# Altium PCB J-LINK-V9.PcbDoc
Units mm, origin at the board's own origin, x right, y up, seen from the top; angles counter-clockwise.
Board outline 88.57 x 38.68 mm, 2 copper layers (Top Layer, Bottom Layer); 76 components, 83 nets, 372 pads, 106 vias.
Unrouted connection lines stored in the file: 2.
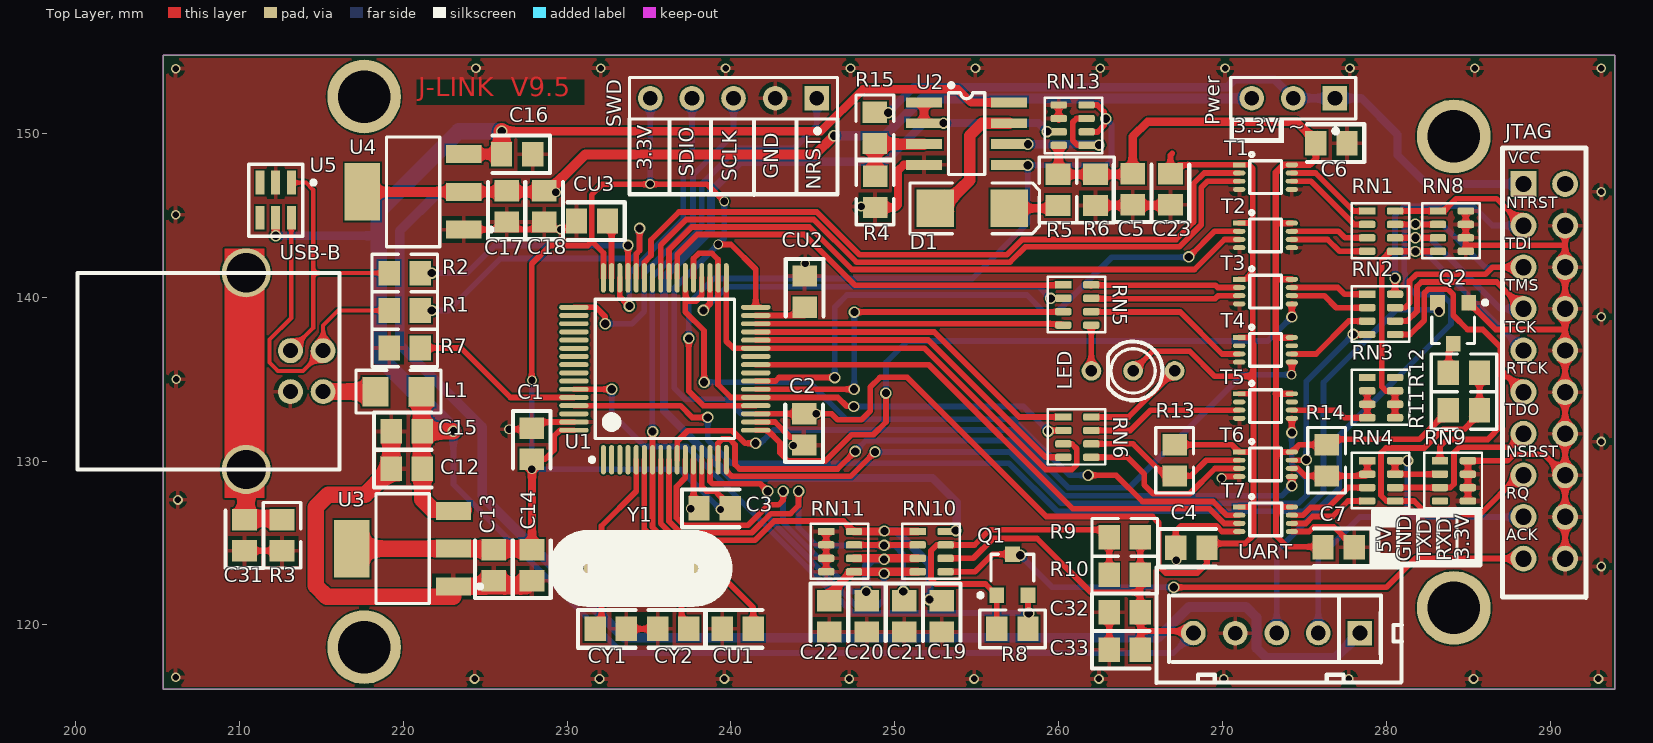
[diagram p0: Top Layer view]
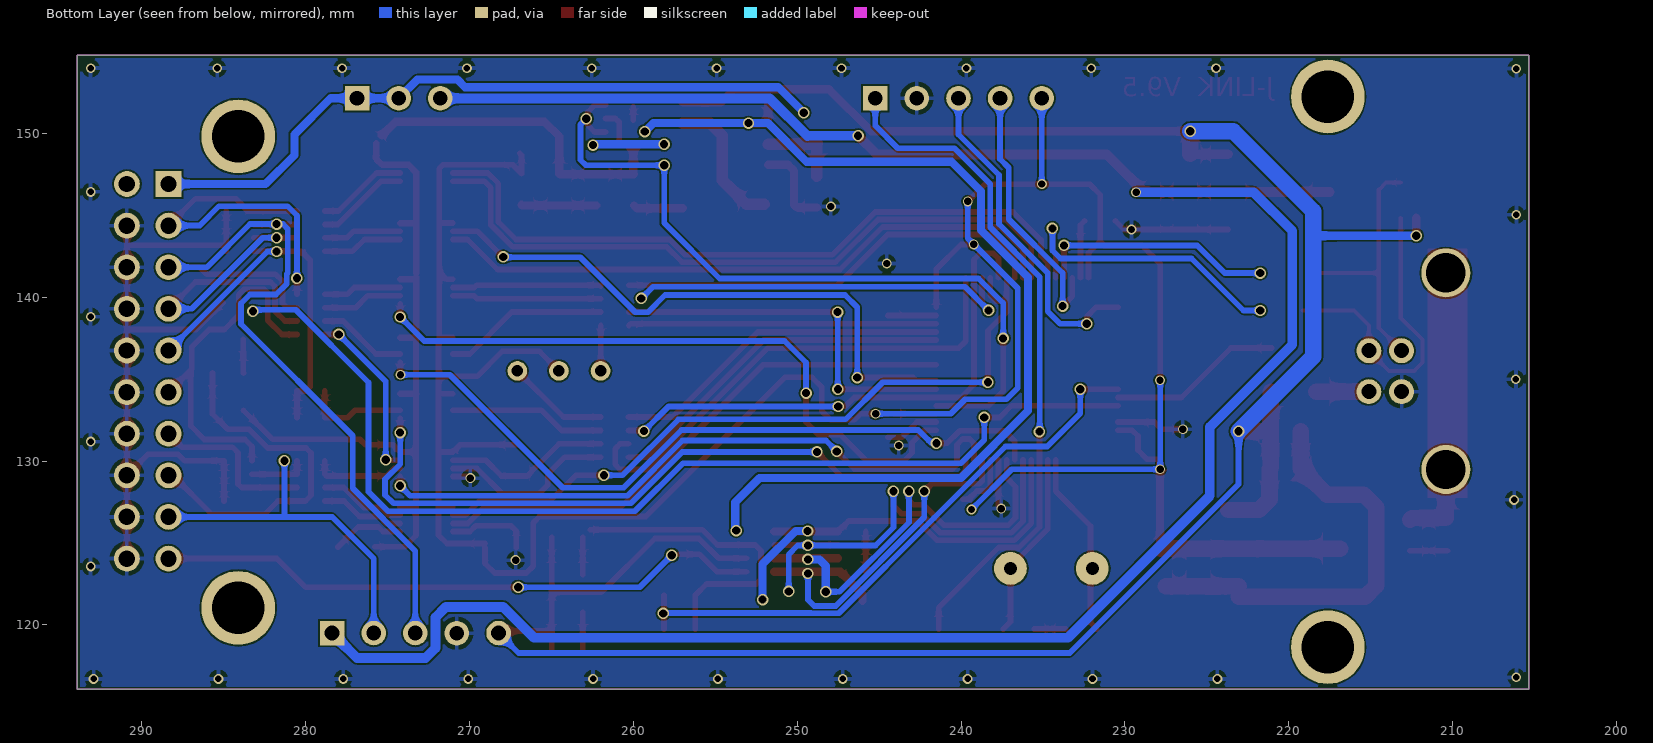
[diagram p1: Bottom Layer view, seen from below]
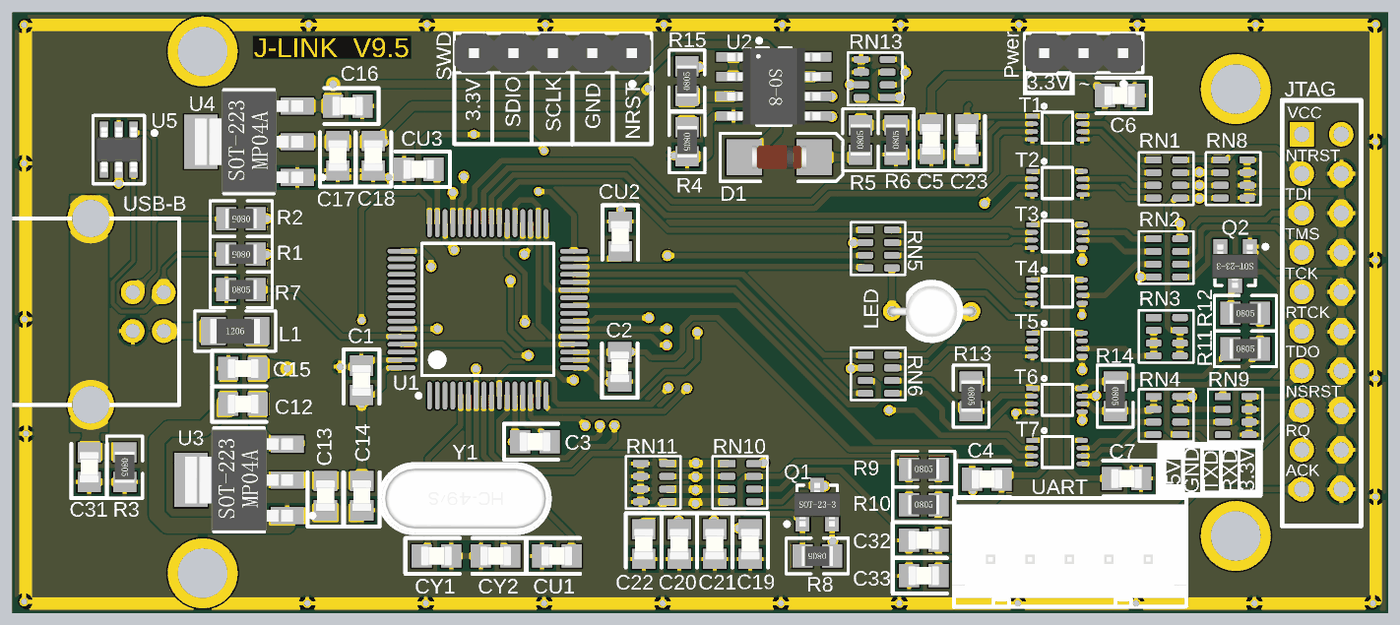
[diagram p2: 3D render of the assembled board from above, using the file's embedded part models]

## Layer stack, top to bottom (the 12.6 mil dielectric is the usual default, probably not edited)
Top Solder: solder mask 0.0102, Solder Resist, Dk 3.5
Top Layer: signal copper 0.0356
Dielectric 1: dielectric 0.32, FR-4, Dk 4.8
Bottom Layer: signal copper 0.0356
Bottom Solder: solder mask 0.0102, Solder Resist, Dk 3.5

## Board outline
205.359,116.078 293.929,116.078 293.929,154.762 205.359,154.762

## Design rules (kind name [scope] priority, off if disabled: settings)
Clearance [All] p1: gap=0.1
PolygonConnect [All] p1: connectstyle=Relief reliefconductorwidth=0.254 reliefentries=4 polygonreliefangle="90 Angle" airgapwidth=0.254
RoutingVias [All] p1: holewidth=0.711 width=1.27 viastyle="Through Hole" minholewidth=0.711 minwidth=1.27 maxholewidth=0.711 maxwidth=1.27
SolderMaskExpansion [All] p1: expansion=0.102
Width [All] p1: maxlimit=2.54 minlimit=2539.975 preferedwidth=0.254 toplayer_minwidth=0 bottomlayer_minwidth=0 minimp=50.000000 maximp=50.000000 favimp=50.000000
30 further rules are at their usual default settings.

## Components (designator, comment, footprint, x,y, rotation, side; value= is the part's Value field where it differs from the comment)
C1 "104" CC2012-0805 227.838,131.064 r270 top
C2 "104" CC2012-0805 244.461,131.939 r90 top
C3 "104" CC2012-0805 239.005,127.119 r0 top
C4 "104" CC2012-0805 268.1,124.706 r0 top
C5 "104" CC2012-0805 264.516,146.591 r90 top (schematic designator C24)
C6 "104" CC2012-0805 276.647,149.406 r180 top (schematic designator C25)
C7 "104" CC2012-0805 277.083,124.746 r180 top (schematic designator C26)
C12 "104" CC2012-0805 220.218,129.54 r0 top
C13 "104" CC2012-0805 225.52,123.648 r90 top
C14 "226" CC2012-0805 227.857,123.648 r90 top
C15 "106" CC2012-0805 220.218,131.826 r0 top
C16 "104" CC2012-0805 226.95,148.728 r180 top
C17 "104" CC2012-0805 226.314,145.542 r90 top
C18 "226" CC2012-0805 228.6,145.542 r90 top
C19 "Cap Chip" CC2012-0805 252.864,120.523 r270 top
C20 "Cap Chip" CC2012-0805 248.292,120.523 r270 top
C21 "Cap Chip" CC2012-0805 250.578,120.523 r270 top
C22 "Cap Chip" CC2012-0805 246.006,120.523 r270 top
C23 "106" CC2012-0805 266.822,146.591 r90 top
C31 "Cap Chip" CC2012-0805 210.312,125.476 r90 top
C32 "Cap Chip" CC2012-0805 264.033,120.777 r0 top
C33 "Cap Chip" CC2012-0805 264.033,118.491 r0 top
CU1 "Cap Chip" CC2012-0805 240.411,119.761 r0 top
CU2 "Cap Chip" CC2012-0805 244.491,140.344 r270 top
CU3 "Cap Chip" CC2012-0805 231.521,144.653 r180 top
CY1 "Cap Chip" CC2012-0805 232.664,119.761 r0 top
CY2 "Cap Chip" CC2012-0805 236.474,119.761 r180 top
D1 "Diode SMT" DSO-C2/X2.3 254.727,145.427 r0 top
JTAG "Header 10X2" IDC2.54-20 288.366,146.914 r270 top locked
L1 "Resistor Chip" CR3216-1206 219.71,134.239 r0 top
LED "LED-3-DOUBLE" LED-R3-H5-DOUBLE 264.541,135.509 r180 top locked
Pwer "Header 3" HDR1X3 276.86,152.146 r180 top
Q1 "PNP-8550" SO-G3/C2.5 257.175,123.063 r0 top
Q2 "NPN-8050" SO-G3/C2.5 284.076,138.422 r180 top
R1 "Resistor Chip" CR2012-0805 220.091,139.192 r180 top
R2 "Resistor Chip" CR2012-0805 220.091,141.478 r180 top
R3 "Resistor Chip" CR2012-0805 212.598,125.476 r270 top
R4 "Resistor Chip" CR2012-0805 248.793,146.431 r270 top
R5 "Resistor Chip" CR2012-0805 259.958,146.555 r90 top
R6 "Resistor Chip" CR2012-0805 262.246,146.555 r90 top
R7 "Resistor Chip" CR2012-0805 220.091,136.906 r0 top
R8 "Resistor Chip" CR2012-0805 257.175,119.761 r180 top
R9 "Resistor Chip" CR2012-0805 264.033,125.349 r0 top
R10 "Resistor Chip" CR2012-0805 264.033,123.063 r0 top
R11 "Resistor Chip" CR2012-0805 284.734,133.096 r0 top
R12 "Resistor Chip" CR2012-0805 284.734,135.382 r0 top
R13 "Resistor Chip" CR2012-0805 267.081,130.048 r270 top
R14 "Resistor Chip" CR2012-0805 276.352,130.048 r270 top
R15 "Resistor Chip" CR2012-0805 248.781,150.338 r90 top
RN1 "RESNET 4 x 220R" SDR 279.654,144.018 r0 top
RN2 "RESNET 4 x 220R" SDR 279.654,138.938 r0 top
RN3 "RESNET 4 x 220R" SDR 279.654,133.858 r0 top
RN4 "RESNET 4 x 220R" SDR 279.654,128.778 r0 top
RN5 "RESNET 4 x 220R" SDR 261.105,139.514 r0 top
RN6 "RESNET 4 x 220R" SDR 261.112,131.445 r0 top
RN8 "RESNET 4 x 220K" SDR 283.972,144.018 r0 top
RN9 "RESNET 4 x 220K" SDR 284.099,128.778 r0 top
RN10 "RESNET 4 x 10K" SDR 252.222,124.46 r0 top
RN11 "RESNET 4 x 10K" SDR 246.634,124.46 r0 top
RN13 "RESNET 4 x 10K" SDR 260.881,150.521 r180 top
SWD "Header 5" HDR1X5 245.237,152.146 r180 top
T1 "2T45" SSOP8 271.018,148.082 r0 top
T2 "2T45" SSOP8 271.018,144.526 r0 top
T3 "2T45" SSOP8 271.018,141.097 r0 top
T4 "2T45" SSOP8 271.018,137.541 r0 top
T5 "2T45" SSOP8 271.018,134.112 r0 top
T6 "2T45" SSOP8 271.018,130.556 r0 top
T7 "2T45" SSOP8 271.021,127.2 r0 top
U1 "STM32F205RCT6" LQFP64_N 235.966,135.636 r90 top
U2 "LM358" SOP-8 254.381,149.987 r270 top locked
U3 "AMS1117-3.3" SOT-223 219.96,124.655 r90 top
U4 "AMS1117-3.3" SOT-223 220.599,146.431 r90 top
U5 "NUP4201" SOP-6 212.217,145.923 r180 top
UART "Header 5" HX2.54-5 278.384,119.507 r180 top
USB-B "Header 6" USB-B 215.113,134.239 r0 top locked
Y1 "XTAL" XTAL-PINGBI 236.986,123.451 r180 top

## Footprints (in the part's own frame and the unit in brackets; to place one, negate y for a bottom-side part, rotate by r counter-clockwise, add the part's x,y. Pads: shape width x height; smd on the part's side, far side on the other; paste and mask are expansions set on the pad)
CC2012-0805 [mm]
  rect 1.3x1.5 smd: 1(-0.95,0) 2(0.95,0)
  silkscreen extent -2,-1.15 1.5,1.15, body extent -1,-0.62 1,0.63, height 0.5
CR2012-0805 [mm]
  rect 1.3x1.5 smd: 1(-0.95,0) 2(0.95,0)
  silkscreen extent -2,-1.15 2,1.15, body extent -1,-0.63 1,0.63, height 0.55
CR3216-1206 [mm]
  rect 1.6x1.8 smd: 1(-1.4,0) 2(1.4,0)
  silkscreen extent -2.6,-1.3 2.6,1.3, body extent -1.6,-0.8 1.6,0.8, height 0.6
DSO-C2/X2.3 [mm]
  rect 2.3x2.3 smd: 1(-2.25,0) 2(2.25,0)
  silkscreen extent -3.8,-1.55 4.1,1.55, body extent -1.75,-0.75 1.75,0.75, height 1.5
HDR1X3 [mm] "Connector; Header; 3 Position"
  rect 1.5x1.5 hole 0.9: 1(0,0)
  round 1.5 hole 0.9: 2(2.54,0) 3(5.08,0)
  silkscreen extent -1.27,-1.27 6.35,2.14, body extent -1.27,-1.27 6.35,1.27, height 8.54
HDR1X5 [mm] "Connector; Header; 5 Position"
  rect 1.5x1.5 hole 0.9: 1(0,0)
  round 1.5 hole 0.9: 2(2.54,0) 3(5.08,0) 4(7.62,0) 5(10.16,0)
  silkscreen extent -1.27,-1.27 11.43,2.14, body extent -1.27,-1.27 11.43,1.27, height 8.54
HX2.54-5 [mm]
  rect 1.5x1.5 hole 0.9: 1(0,0)
  round 1.5 hole 0.9: 2(2.54,0) 3(5.08,0) 4(7.607,0.006) 5(10.16,0)
  silkscreen extent -2.55,-4.06 12.42,3.05, body extent -2.56,-3.56 12.52,2.44, height 7.51
IDC2.54-20 [mil]
  rect 62x62 hole 39.37: 1(0,0)
  round 62 hole 39.37: 2(0,100) 3(100,0) 4(100,100) 5(200,0) 6(200,100) 7(300,0) 8(300,100) 9(400,0) 10(400,100) 11(500,0) 12(500,100) 13(600,0) 14(600,100) 15(700,0) 16(700,100) 17(800,0) 18(800,100) 19(900,0) 20(900,100)
  silkscreen extent -86,-50 994,150
LED-R3-H5-DOUBLE [mm]
  round 1.2 hole 0.7: 1(0,0) 2(-2.54,0) 3(2.54,0)
  silkscreen extent -1.8,-1.79 1.52,1.79, body extent -2.79,-2.04 2.79,2.04, height 5.7
LQFP64_N [mm]
  oval 1.8x0.3 smd: 1(-5.55,3.75) 2(-5.55,3.25) 3(-5.55,2.75) 4(-5.55,2.25) 5(-5.55,1.75) 6(-5.55,1.25) 7(-5.55,0.75) 8(-5.55,0.25) 9(-5.55,-0.25) 10(-5.55,-0.75) 11(-5.55,-1.25) 12(-5.55,-1.75) 13(-5.55,-2.25) 14(-5.55,-2.75) 15(-5.55,-3.25) 16(-5.55,-3.75) 33(5.55,-3.75) 34(5.55,-3.25) 35(5.55,-2.75) 36(5.55,-2.25) 37(5.55,-1.75) 38(5.55,-1.25) 39(5.55,-0.75) 40(5.55,-0.25) 41(5.55,0.25) 42(5.55,0.75) 43(5.55,1.25) 44(5.55,1.75) 45(5.55,2.25) 46(5.55,2.75) 47(5.55,3.25) 48(5.55,3.75)
  oval 0.3x1.8 smd: 17(-3.75,-5.55) 18(-3.25,-5.55) 19(-2.75,-5.55) 20(-2.25,-5.55) 21(-1.75,-5.55) 22(-1.25,-5.55) 23(-0.75,-5.55) 24(-0.25,-5.55) 25(0.25,-5.55) 26(0.75,-5.55) 27(1.25,-5.55) 28(1.75,-5.55) 29(2.25,-5.55) 30(2.75,-5.55) 31(3.25,-5.55) 32(3.75,-5.55) 49(3.75,5.55) 50(3.25,5.55) 51(2.75,5.55) 52(2.25,5.55) 53(1.75,5.55) 54(1.25,5.55) 55(0.75,5.55) 56(0.25,5.55) 57(-0.25,5.55) 58(-0.75,5.55) 59(-1.25,5.55) 60(-1.75,5.55) 61(-2.25,5.55) 62(-2.75,5.55) 63(-3.25,5.55) 64(-3.75,5.55)
  silkscreen extent -5.67,-4.25 4.25,4.57
SDR [mm]
  rect 1x0.45 smd: 1(-0.824,1.248)
  rrect50% 1x0.45 smd: 2(-0.824,0.427) 3(-0.824,-0.393) 4(-0.824,-1.212) 5(0.875,-1.212) 6(0.875,-0.393) 7(0.875,0.427) 8(0.875,1.248)
  silkscreen extent -1.78,-1.65 1.74,1.73
SO-G3/C2.5 [mm]
  rect 0.9x0.95 smd: 1(-0.95,-1.25) 2(0.95,-1.25) 3(0,1.25)
  silkscreen extent -2.07,-1.37 1.3,1.25, body extent -1.45,-1.4 1.45,1.4, height 1.2
SOP-6 [mm]
  rect 0.55x1.45 smd: 1(-0.95,-1.075) 2(0,-1.075) 3(0.95,-1.075) 4(0.95,1.075) 5(0,1.075) 6(-0.95,1.075)
  silkscreen extent -2.43,-2.2 1.65,2.2, body extent -1.48,-1.43 1.49,1.43, height 1.26
SOP-8 [mm]
  rect 0.6x2.2 smd: 1(-1.905,-2.6) 2(-0.635,-2.6) 3(0.635,-2.6) 4(1.905,-2.6) 5(1.905,2.6) 6(0.635,2.6) 7(-0.635,2.6) 8(-1.905,2.6)
  silkscreen extent -3.07,-1.1 2.5,1.1, body extent -2.45,-3 2.45,3, height 1.7
SOT-223 [mm]
  rect 1.1x2.15 smd: 1(-2.3,-3.1) 2(0,-3.1) 3(2.3,-3.1)
  rect 3.5x2.15 smd: 2(0,3.1)
  silkscreen extent -3.35,-4.85 3.35,1.63, body extent -3.25,-3.48 3.25,3.48, height 1.7
SSOP8 [mm]
  rect 0.75x0.3 smd: 1(0,0)
  oval 0.75x0.3 smd: 2(0,-0.5) 3(0,-1) 4(0,-1.5) 5(3.212,-1.5) 6(3.212,-1) 7(3.212,-0.5) 8(3.212,0)
  silkscreen extent 0.64,-1.75 2.59,0.76, body extent 0.51,-1.91 2.73,0.38, height 1.3
USB-B [mm]
  round 1.524 hole 0.92: 1(0,0) 2(0,2.5) 3(-2,2.5) 4(-2,0)
  round 3 hole 2.4: 5(-4.7,7.25) 6(-4.7,-4.75)
  silkscreen extent -15,-4.75 1,7.25, body extent -15.05,-4.8 1.11,7.32, height 10.1
XTAL-PINGBI [mm]
  round 2 hole 0.8: 1(0,0) 2(5,0)
  silkscreen extent -3,-2.25 8,2.26, body extent -2.95,-2.26 7.85,2.24, height 3.5

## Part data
C1 C2 C3 C4 C5 C6 C7 C12 C13 C14 C15 C16 C17 C18 C23: library part "Cap Chip", "Polarized Capacitor (Radial)"
C19 C20 C21 C22 C31 C32 C33 CU1 CU2 CU3 CY1 CY2: "Polarized Capacitor (Radial)"
D1: "Default Diode"
JTAG: "Header, 10-Pin, Dual row"
L1 R1 R2 R3 R4 R5 R6 R7 R8 R9 R10 R11 R12 R13 R14 R15: "Resistor"
LED: "Typical INFRARED GaAs LED"
Pwer: "Header, 3-Pin"
Q1: library part PNP-SMT, "PNP Bipolar Transistor"
Q2: library part NPN-SMT, "NPN Bipolar Transistor"
RN1 RN2 RN3 RN4 RN5 RN6 RN8 RN9 RN10 RN11 RN13: library part "Res Pack SMT4", "Resistor Network, Isolated, 4 x 100R, 5%, SMD 0402 x 4"
SWD UART: "Header, 5-Pin"
T1 T2 T3 T4 T5 T6 T7: library part Component_1
U1: library part STM32F103RDT6
U2: library part LM393
U3 U4: library part AMS1117, "POSITIVE OUTPUT VOLTAGE"
U5: library part USBLC6
USB-B: "Header, 6-Pin"
Y1: "Crystal Oscillator"

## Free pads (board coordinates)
  round 4.5 hole 3.2: 0(217.614,118.646) 0(217.614,152.246) 0(284.114,121.046) 0(284.114,149.821)

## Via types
v1: diameter 0.7, hole 0.5, Top Layer to Bottom Layer, 60 vias
v2: diameter 0.6, hole 0.4, Top Layer to Bottom Layer, 29 vias
v3: diameter 0.6, hole 0.45, Top Layer to Bottom Layer, 17 vias

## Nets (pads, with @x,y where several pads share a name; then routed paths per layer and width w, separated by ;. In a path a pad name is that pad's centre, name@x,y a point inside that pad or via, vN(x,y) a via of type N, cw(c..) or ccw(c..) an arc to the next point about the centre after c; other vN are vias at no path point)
3.3V-A: C1.2 C2.2 C3.2 C4.2 C13.2 C14.2 C23.2 LED.1 R13.1 SWD.5 T1.1 T2.1 T3.1 T4.1 T5.1 T6.1 T7.1 U1.13 U1.19 U1.32 U1.48 U1.64 U3.2 | length 186.2
  Top Layer w0.35: C1.2 228.644,130.114 229.206,130.676 229.206,131.532 229.561,131.886 U1.64 ; v3@227.843,135.078 227.843,142.05 228.954,143.161 231.258,143.161 231.496,143.398 231.496,146.248 232.146,146.898 238.543,146.898 v3(239.591,145.851) ; 231.441,143.344 231.579,143.344 232.216,142.706 U1.48 ; U1.13 238.216,128.442 238.487,128.17 239.034,128.17 239.524,127.68 C3.2@239.878,127.68 ; v3(239.226,143.226) 239.994,143.226 241.516,141.704 U1.32 ; U1.19 C2.2@244.111,132.886 ; C2.2 246.144,132.889 246.507,132.526 247.967,132.526 248.499,133.059 248.499,134.519 249.091,135.111 250.762,135.111 259.246,126.627 265.724,126.627 266.11,126.24 266.11,123.586 266.531,123.166 268.458,123.166 269.05,123.758 C4.2 ; LED.1 265.73,136.698 268.007,136.698 269.531,135.174 271.883,135.174 ; 266.931,148.783 266.822,148.675 C23.2 267.363,148.082 T1.1 271.615,148.082 271.852,147.845 271.852,141.543 ; R13.1 270.576,130.998 T6.1 271.792,130.556 ; C4.2@269.05,124.968 271.373,124.968 271.883,125.478 271.883,135.174 ; T5.1 271.869,134.112 ; T4.1 271.714,137.541 271.852,137.403 ; T3.1 271.406,141.097 271.852,141.543 ; T2.1 271.843,144.526 ; T7.1 271.832,127.2 ; 271.852,137.112 271.852,137.403 ; 271.883,137.112 271.883,135.174 ; 271.852,137.403 271.852,141.543
  Top Layer w0.5: C14.2 C1.2@227.857,129.833
  Top Layer w1: U3.2@216.86,124.655 223.06,124.655 C14.2@227.8,124.655
  Bottom Layer w0.35: v3(227.856,134.933) 227.849,134.926 v3(227.849,129.501) 236.908,129.501 v3(239.359,127.05) ; v3(235.065,146.912) 235.077,146.924 SWD.5 ; v3@239.59,145.912 239.59,143.596 236.543,140.548 236.543,134.463 237.229,133.777 239.74,133.777 240.629,132.888 v3(245.213,132.888)
3.3V-B: C17.2 C18.2 Pwer.3 U4.2 UART.1 | length 146.2
  Top Layer w0.6: U4.2@217.499,146.431 228.539,146.431 C18.2 228.883,146.492 231.105,148.714 245.141,148.714 v1(246.283,149.857)
  Bottom Layer w0.6: v3(229.316,146.41) 222.155,146.41 219.783,144.037 219.783,137.119 224.818,132.084 224.818,127.886 233.481,119.223 266.063,119.223 267.935,121.095 271.447,121.095 272.075,120.467 272.075,118.583 272.679,117.979 276.856,117.979 UART.1 ; v1(246.283,149.857) 249.364,149.857 249.378,149.843 251.673,152.138 271.331,152.138 Pwer.3@271.552,151.918
5V: C12.2 C15.2 C16.2 C32.2 C33.2 L1.2 R9.2 R10.2 RN10.6 U2.8 U3.3 U4.3 U5.5 UART.5 | length 156.3
  Top Layer w0.35: RN10.6 254.79,124.067 256.007,125.285 258.672,125.285 261.962,121.995 264.983,121.995 ; C33.2 264.983,119.627 ; R9.2 R10.2 264.983,121.995 ; UART.5@268.104,119.627 264.983,119.627 ; 264.983,119.627 C32.2 264.983,121.995
  Top Layer w0.5: v1@212.217,143.918 U5.5 ; v1(226.017,150.138) 245.494,150.138 248.046,152.69 253.861,152.69 254.66,151.892 U2.8
  Top Layer w0.6: U4.3 225.998,148.731 C16.2
  Top Layer w1: C12.2@221.11,129.598 L1.2 ; C12.2 221.168,127.658 221.812,127.014 U3.3@223.699,127.014 ; C15.2 v1@223.061,131.826 ; C16.2@226.017,148.745 v1(226.017,150.138)
  Bottom Layer w0.35: v1(223.062,131.826) 223.062,128.593 233.371,118.284 267.001,118.284 UART.5
  Bottom Layer w0.5: v1(212.218,143.754) 218.555,143.754
  Bottom Layer w1: v1(223.062,131.826) 218.499,136.389 218.499,145.256 223.381,150.138 v1(226.017,150.138)
ACK-D: RN10.8 RN13.7 U2.1 U2.2 | length 61.4
  Top Layer w0.5: U2.1 U2.2 v1@252.97,150.622
  Bottom Layer w0.5: v1@253.785,125.811 253.785,127.486 252.293,128.979 240.011,128.979 235.917,133.073 235.917,141.221 238.786,144.09 238.786,146.469 240.586,148.269 249.43,148.269 251.788,150.627 v1(252.97,150.627) 258.782,150.627 v1(259.3,150.11)
  other v1: 253.724,125.763
BOOT0: R7.2 U1.60 | length 10.6
  Top Layer w0.35: R7.2 223.52,136.906 226.54,133.886 U1.60
BOOT1: RN6.4 U1.28 | length 21.7
  Top Layer w0.35: U1.28 252.039,137.386 259.192,130.233 RN6.4
BOOT2: U1.58
BOOT3: U1.57
DM: R1.1 U1.44 | length 18.6
  Top Layer w0.35: U1.44 234.216,142.649 234.422,142.855 v1(234.422,144.201)
  Bottom Layer w0.35: v1(221.742,139.192) 222.758,139.192 225.933,142.367 233.932,142.367 234.422,142.857 v1(234.422,144.201)
DM1: R1.2 U5.6 USB-B.2 | length 19.3
  Top Layer w0.254: U5.6 213.167,138.745 211.836,137.414 211.836,136.017 212.344,135.509 213.883,135.509 USB-B.2 215.113,138.278 216.027,139.192 R1.2
DP: R2.1 U1.45 | length 14.7
  Top Layer w0.35: U1.45 v1(233.716,143.165)
  Bottom Layer w0.35: v1(221.742,141.478) 223.901,141.478 225.588,143.165 v1(233.716,143.165)
DP1: R2.2 U5.1 USB-B.3 | length 16.4
  Top Layer w0.254: USB-B.3 214.503,138.129 214.503,146.558 214.063,146.998 U5.1 ; 214.503,141.478 218.633,141.478 R2.2@218.887,141.732
GND: C1.1 C2.1 C3.1 C4.1 C5.1 C6.1 C7.1 C12.1 C13.1 C14.1 C15.1 C16.1 C17.1 C18.1 C19.2 C20.2 C21.2 C22.2 C23.1 C31.1 C32.1 C33.1 CU1.1 CU2.1 CU3.2 CY1.2 CY2.2 JTAG.4 JTAG.6 JTAG.8 JTAG.10 JTAG.12 JTAG.14 JTAG.16 JTAG.18 JTAG.20 Q2.1 R3.2 R4.2 R6.1 R7.1 RN8.5 RN8.6 RN8.7 RN8.8 RN9.5 RN9.6 RN9.7 RN9.8 RN11.1 RN11.2 RN11.3 RN11.4 RN13.5 RN13.6 SWD.2 T1.4 T1.5 T2.4 T2.5 T3.4 T4.4 T5.4 T6.4 T7.4 T7.5 U1.12 U1.18 U1.63 U2.4 U3.1 U4.1 U5.2 UART.4 USB-B.4 | length 118.1
  Top Layer w0.35: C31.1 R3.2 ; U4.1 230.049,144.131 CU3.2 ; v3(226.461,131.942) 227.766,131.942 C1.1 228.21,132.386 U1.63 ; CY1.2 CY2.2 ; C3.1@237.716,127.261 U1.12 ; U1.18 242.684,132.386 243.615,131.455 C2.1@244.451,131.455 ; RN11.4 RN11.3 RN11.2 RN11.1 ; RN13.6@259.998,150.813 RN13.5@259.998,151.633 ; C33.1 C32.1 ; C4.1 267.15,125.729 267.48,126.059 269.616,126.059 269.975,125.7 T7.4 ; v3(269.944,128.965) 270.035,129.056 T6.4 ; T7.5 275.277,125.7 275.56,125.983 276.796,125.983 C7.1 ; RN8.5 284.847,143.335 ; RN8.8 RN8.7 RN8.6 284.847,143.335 ; RN9.5 RN9.6 RN9.7 RN9.8 287.389,130.026 287.786,130.422 289.618,130.422 JTAG.16 ; Q2.1 286.668,138.03 290.895,138.03 ; JTAG.20 JTAG.18 JTAG.16 ; JTAG.4 290.906,143.247 ; 284.847,143.335 285.015,143.167 290.827,143.167 290.906,143.247 ; JTAG.16 JTAG.14 JTAG.12 JTAG.10 JTAG.8 JTAG.6 290.906,143.247
  Top Layer w0.5: R4.2 250.028,145.481 250.187,145.64 250.187,147.723 250.546,148.082 U2.4 ; R6.1 266.786,145.605 C23.1
  Top Layer w1: C15.1 C12.1 217.687,127.959 215.427,127.959 214.662,127.194 214.662,122.399 215.347,121.714 223.06,121.714 ; U3.1 C14.1@227.514,122.355
  other v2: 224.358,116.713 231.978,116.713 239.598,116.713 247.218,116.713 254.838,116.713 262.458,116.713 270.078,116.713 277.698,116.713 285.318,116.713 292.938,116.713 206.121,116.815 293.116,123.571 206.248,127.635 293.116,131.191 206.146,135.001 293.116,138.811 206.121,145.034 293.116,146.431 206.121,153.949 224.434,153.975 232.054,153.975 239.674,153.975 247.294,153.975 254.914,153.975 262.534,153.975 270.154,153.975 277.774,153.975 285.394,153.975 293.116,153.975
  other v3: 267.184,123.958 237.548,127.104 243.798,130.955 244.534,142.061 229.594,144.137 247.943,145.538
L1: LED.3 RN5.5 | length 2.8
  Top Layer w0.35: RN5.5@261.985,138.276 261.985,135.525 LED.3
L2: LED.2 RN6.8 | length 6.3
  Top Layer w0.35: RN6.8 264.265,132.693 LED.2
LED1: RN5.4 U1.30 | length 18.8
  Top Layer w0.35: U1.30 260.176,138.386 RN5.4@260.285,138.276
LED2: RN6.1 U1.29 | length 20.9
  Top Layer w0.35: U1.29 252.404,137.886 257.598,132.693 RN6.1
NetC31_2: C31.2 R3.1 USB-B.5 USB-B.6 | length 17.2
  Top Layer w1: USB-B.5 USB-B.6 210.413,126.527 212.497,126.527 R3.1
NetCU2_2: CU2.2 U1.31 | length 3
  Top Layer w0.35: U1.31 244.466,138.886 CU2.2@244.475,138.877
NetCU3_1: CU3.1 U1.47 | length 3.6
  Top Layer w0.35: CU3.1 232.716,144.408 U1.47
NetD1_1: D1.1 U2.7 | length 8.6
  Top Layer w0.7: D1.1@252.004,145.669 253.097,145.669 254.567,147.139 254.567,149.873 255.316,150.622 U2.7
NetD1_2: D1.2 R5.1 | length 3.1
  Top Layer w0.5: D1.2 259.78,145.427 R5.1
NetL1_1: L1.1 USB-B.1 | length 3.2
  Top Layer w1: USB-B.1 L1.1
NetQ2_3: Q2.3 R12.1 | length 2.1
  Top Layer w0.35: R12.1 283.8,135.398 Q2.3@283.8,137.435
NetR13_2: R13.2 RN6.6 T6.2 | length 10.2
  Top Layer w0.35: RN6.6 264.536,131.052 266.491,129.098 R13.2 268.054,129.098 269.012,130.056 T6.2
NetR14_2: R14.2 RN4.1 RN4.2 T6.6 | length 5.7
  Top Layer w0.35: T6.6 274.591,129.556 275.049,129.098 R14.2 278.722,129.098 RN4.2 RN4.1
NetRN1_1: RN1.1 T1.7 | length 5.6
  Top Layer w0.35: T1.7 275.672,147.582 277.988,145.266 RN1.1
NetRN1_2: RN1.2 T1.6 | length 5.7
  Top Layer w0.35: T1.6 275.398,147.082 278.034,144.445 RN1.2
NetRN1_3: RN1.3 T2.7 | length 4.8
  Top Layer w0.35: T2.7 277.084,144.026 277.484,143.625 RN1.3
NetRN1_4: RN1.4 T2.6 | length 4.9
  Top Layer w0.35: T2.6 276.411,143.526 277.132,142.806 RN1.4
NetRN2_1: RN2.1 T3.7 | length 4.8
  Top Layer w0.35: T3.7 277.028,140.597 277.44,140.186 RN2.1
NetRN2_2: RN2.2 T3.6 | length 4.9
  Top Layer w0.35: T3.6 276.215,140.097 276.946,139.365 RN2.2
NetRN2_3: RN2.3 T4.6 | length 5.4
  Top Layer w0.35: T4.6 275.701,136.541 277.705,138.545 RN2.3
NetRN2_4: RN2.4 T6.7 | length 10.4
  Top Layer w0.35: T6.7 v1@274.937,130.056 ; v1@277.986,137.726 RN2.4
  Bottom Layer w0.35: v1(275.114,130.083) 275.114,134.868 v1(277.978,137.733)
NetRN3_2: RN3.2 RN3.3 RN3.4 T5.6 | length 6.4
  Top Layer w0.35: T5.6 276.971,133.112 277.438,132.646 RN3.4 RN3.3 RN3.2
NetRN4_3: RN4.3 T7.7 | length 5.3
  Top Layer w0.35: T7.7 274.917,126.7 275.384,127.168 276.45,127.168 277.668,128.385 RN4.3
NetRN4_4: RN4.4 T7.6 | length 5.2
  Top Layer w0.35: T7.6 275.074,126.2 275.5,126.626 276.716,126.626 277.656,127.566 RN4.4
NetRN5_6: RN5.6 T4.3 | length 10.1
  Top Layer w0.35: RN5.6@261.985,139.096 267.421,139.096 269.977,136.541 T4.3
NetRN5_7: RN5.7 T3.3 | length 9.1
  Top Layer w0.35: RN5.7@261.985,139.916 269.554,139.916 269.735,140.097 T3.3
NetRN5_8: RN5.8 T3.2 | length 9.2
  Top Layer w0.35: RN5.8@261.985,140.736 RN5.8@262.03,140.736 ; RN5.8@261.987,140.694 RN5.8@262.03,140.736 ; T3.2 269.714,140.597 269.575,140.736 RN5.8@262.03,140.736
NetRN6_5: RN6.5 T6.3 | length 11
  Top Layer w0.35: RN6.5 264.199,130.233 265.218,129.213 265.218,128.546 265.751,128.014 268.005,128.014 269.547,129.556 T6.3
NetRN6_7: RN6.7 T5.3 | length 9.5
  Top Layer w0.35: RN6.7 264.374,131.872 265.614,133.112 T5.3
NetRN13_1: RN13.1 RN13.3 U2.6 | length 7.4
  Top Layer w0.35: RN13.1 261.156,149.273 260.856,149.573 260.856,150.676 261.093,150.913 RN13.3
  Bottom Layer w0.5: v1(258.123,149.344) 262.404,149.344 v1(262.462,149.286)
NRST: CU1.2 SWD.1 U1.7 | length 41.8
  Top Layer w0.35: v1(235.216,131.806) U1.7 235.216,125.982 236.471,124.726 237.706,124.726 241.361,121.071 CU1.2
  Bottom Layer w0.35: v1@235.194,131.806 235.194,141.24 238.222,144.269 238.222,146.915 240.404,149.097 243.858,149.097 245.237,150.475 SWD.1
NSRST-Y: JTAG.15 R11.2 R12.2 RN4.5 | length 22.3
  Top Layer w0.35: R12.2 R11.2 285.684,132.876 284.749,131.941 283.46,131.941 282.314,130.794 279.971,130.794 279.668,130.491 279.668,127.91 280.013,127.566 RN4.5 281.684,127.566 282.502,126.748 285.722,126.748 288.107,129.134 JTAG.15
NTRST-Y: JTAG.3 RN1.8 RN2.8 RN8.1 | length 22.2
  Top Layer w0.35: RN2.8 v1(280.53,141.166) ; RN1.8 RN8.1 283.511,145.266 284.266,146.02 286.72,146.02 JTAG.3
  Bottom Layer w0.35: v1(280.53,141.166) 280.53,144.987 281.105,145.562 285.278,145.562 286.466,144.374 JTAG.3
PWR-Y: JTAG.19 Q1.3 RN10.5 | length 36.8
  Top Layer w0.35: RN10.5 254.9,123.248 255.965,124.313 Q1.3 ; v1@267.019,122.3 280.009,122.3 281.763,124.054 JTAG.19
  Bottom Layer w0.35: v1(257.653,124.259) 259.613,122.3 v1@267.019,122.3
  other v1: 267.019,122.3
RTCK-Y: JTAG.11 RN2.5 RN9.1 | length 22.6
  Top Layer w0.35: RN2.5 281.446,137.726 282.312,138.591 282.312,140.257 282.537,140.482 283.776,140.482 284.085,140.173 284.085,138.903 284.951,138.038 285.884,138.038 286.951,136.971 286.951,135.629 287.004,135.576 ; RN9.1 283.275,130.899 283.693,131.318 286.184,131.318 287.004,132.138 287.004,135.576 ; JTAG.11 287.004,135.576
RXD-Y: JTAG.17 RN4.7 RN4.8 RN9.2 UART.2 | length 25.1
  Top Layer w0.35: RN4.8 RN4.7 RN9.2
  Bottom Layer w0.35: UART.2 275.844,124.06 278.378,126.594 281.077,126.594 JTAG.17 ; 281.292,126.627 v1(281.292,130.02)
SDB1: Q2.2 U1.61 | length 65.3
  Top Layer w0.35: U1.61 236.915,133.386 237.632,132.669 v1(238.588,132.669)
  Bottom Layer w0.35: v1(238.588,132.669) 238.588,131.284 239.997,129.876 256.975,129.876 259.91,126.94 274.973,126.94 276.167,128.134 276.167,134.801 280.602,139.237 v1@283.202,139.237
  other v1: 283.219,139.153
SDB3: T1.2 U1.43 | length 43.6
  Top Layer w0.35: U1.43 234.716,142.133 235.126,142.543 235.126,143.496 236.827,145.198 245.238,145.198 247.842,142.594 256.842,142.594 257.775,143.526 267.168,143.526 268.236,144.594 268.236,146.938 268.88,147.582 T1.2
SDB4: T1.3 U1.41 | length 42.4
  Top Layer w0.35: U1.41 235.716,143.189 237.275,144.748 245.052,144.748 247.656,142.144 257.029,142.144 257.961,143.076 267.355,143.076 268.707,144.428 268.707,146.703 269.087,147.082 T1.3
SDB5: T2.3 U1.40 | length 38.9
  Top Layer w0.35: U1.40 236.216,142.902 237.606,144.292 244.785,144.292 247.383,141.694 268.284,141.694 270.117,143.526 T2.3
SDB6: RN5.1 U1.39 | length 26.8
  Top Layer w0.35: U1.39 236.716,142.605 237.945,143.835 244.478,143.835 247.576,140.736 RN5.1@260.285,140.736
SDB7: T7.2 U1.36 U1.38 | length 45.2
  Top Layer w0.35: U1.38 237.216,139.974 ; U1.36 238.216,140.106 237.866,139.756 237.434,139.756 237.216,139.974 ; v1(238.359,134.812) 238.359,137.964 237.216,139.108 237.216,139.974 ; v1(261.794,129.142) 263.506,129.142 265.111,127.536 269.411,127.536 270.247,126.7 T7.2
  Bottom Layer w0.35: v1(238.359,134.812) 244.781,134.812 247.045,132.548 257.251,132.548 260.664,129.135 260.671,129.142 v1(261.794,129.142)
SDB8: RN6.2 U1.21 U1.34 U1.37 | length 32.9
  Top Layer w0.35: U1.37 237.716,142.36 238.036,142.68 238.84,142.68 239.216,142.304 U1.34 239.216,134.668 239.998,133.886 U1.21 246.522,133.886 247.06,133.348 v1@247.493,133.348 ; v1@259.352,131.872 RN6.2
  Bottom Layer w0.35: v1(247.493,133.333) 257.822,133.333 257.837,133.348 v1(259.352,131.833)
SDB10: RN5.2 U1.35 | length 24.1
  Top Layer w0.35: v1@238.389,139.266 238.716,139.593 U1.35
  Bottom Layer w0.35: v1(238.319,139.196) 239.773,140.65 258.789,140.65 v1(259.512,139.926)
SDB14: RN6.3 U1.27 U1.33 | length 30.5
  Top Layer w0.35: U1.33 239.716,137.318 240.148,136.886 U1.27 251.818,136.886 259.213,129.491 260.806,129.491 261.106,129.791 261.106,130.759 260.812,131.052 RN6.3
SDB15: T7.3 U1.25 | length 33.5
  Top Layer w0.35: U1.25 252.067,135.886 260.867,127.086 269.225,127.086 270.111,126.2 T7.3
SDB16: T2.2 U1.23 | length 36.5
  Top Layer w0.35: U1.23 242.719,134.886 242.935,135.102 v1(246.34,135.103) ; v1@268.043,142.558 269.511,144.026 T2.2
  Bottom Layer w0.35: v1(246.34,135.103) 246.34,139.395 247.08,140.136 258.059,140.136 259.106,139.089 259.883,139.089 263.236,142.442 v1@267.955,142.442
  other v1: 267.941,142.459
SDB17: RN5.3 U1.22 | length 23.5
  Top Layer w0.35: U1.22 v1(247.518,134.386) ; v1(247.532,139.096) RN5.3@260.285,139.096
  Bottom Layer w0.35: v1(247.518,134.386) v1@247.518,139.082
SDB19: RN13.2 RN13.4 U1.20 U2.5 | length 47.3
  Top Layer w0.35: v1(237.431,137.491) 237.43,134.267 238.312,133.386 U1.20 ; RN13.2 262.373,150.093 262.775,150.495 262.775,151.312 262.354,151.733 RN13.4
  Bottom Layer w0.35: v1(237.431,137.491) 237.431,139.644 238.938,141.152 254.732,141.152 258.118,144.537 v1(258.118,148.054) 262.895,148.054 263.228,148.386 263.228,150.541 v1(262.871,150.898)
SDB20: T3.5 U1.17 | length 40.4
  Top Layer w0.35: U1.17 242.232,131.886 242.992,131.126 242.992,130.503 243.486,130.009 245.756,130.009 247.351,131.604 248.682,131.604 249.46,132.382 v1(249.46,134.156) ; v1(274.23,138.797) T3.5
  Bottom Layer w0.35: v1(249.46,134.156) 249.46,136.021 250.77,137.331 272.765,137.331 v1(274.23,138.797)
SDB21: T5.5 U1.16 | length 43.4
  Top Layer w0.35: U1.16 239.716,129.396 240.042,129.07 241.969,129.07 241.97,129.069 247.3,129.069 v1@248.791,130.56 ; v1(274.23,131.741) T5.5
  Bottom Layer w0.35: v1(248.791,130.56) 257.013,130.56 260.144,127.429 274.64,127.429 275.149,127.938 275.149,128.894 274.218,129.825 274.23,129.838 v1(274.23,131.741)
SDB22: T6.5 U1.15 | length 40.7
  Top Layer w0.35: U1.15 239.216,131.097 239.463,131.344 239.913,131.344 240.253,131.004 240.253,129.791 240.523,129.52 246.51,129.52 v1(247.586,130.596) ; v1@274.23,128.501 T6.5
  Bottom Layer w0.35: v1(247.586,130.596) 248.248,131.258 256.997,131.258 260.376,127.879 273.612,127.879 v1(274.233,128.499) ; v1@274.153,128.657 274.153,128.513 v1@274.191,128.552
SDB23: C22.1 RN10.4 RN11.5 U1.14 | length 24.2
  Top Layer w0.35: U1.14 238.716,128.773 238.869,128.62 241.783,128.62 v1(242.24,128.162)
  Top Layer w0.5: C22.1 246.006,121.89 247.364,123.248 RN11.5 RN10.4
  Bottom Layer w0.35: v1(242.24,128.162) 242.24,126.569 247.647,121.163 248.962,121.163 249.341,121.542 v1(249.341,123.143)
SDB24: C20.1 RN10.3 RN11.6 U1.11 | length 27.1
  Top Layer w0.35: U1.11 237.216,128.98 236.67,128.434 236.67,126.544 237.135,126.079 241.028,126.079 242.28,127.331 242.896,127.331 243.183,127.618 v1(243.183,128.162)
  Top Layer w0.5: RN11.6 RN10.3
  Bottom Layer w0.35: v1(243.183,128.162) 243.183,126.263 247.416,122.03 v1(248.261,122.03)
  Bottom Layer w0.5: v1(248.261,122.03) 248.261,123.617 248.642,123.999 v1(249.341,123.999)
SDB25: T4.5 U1.10 | length 44.6
  Top Layer w0.35: U1.10 236.716,131.217 237.359,131.859 240.084,131.859 240.857,131.086 v1(241.5,131.086) ; v3@274.23,135.352 T4.5
  Bottom Layer w0.35: v1(241.5,131.086) 241.799,131.086 242.61,131.897 257.065,131.897 260.592,128.371 264.309,128.371 271.206,135.268 274.147,135.268 v3@274.23,135.352
  other v3: 274.212,135.268
SDB27: C19.1 RN10.1 RN11.8 U1.8 | length 26.5
  Top Layer w0.35: U1.8 235.716,126.193 236.733,125.176 237.892,125.176 237.894,125.174 241.471,125.174 242.641,126.345 246.872,126.345 RN11.8
  Top Layer w0.5: RN11.8 RN10.1
  Bottom Layer w0.5: v1(249.363,125.735) 250.088,125.735 252.113,123.71 v1(252.113,121.549)
SEY1: Q1.1 R8.2 R9.1 R10.1 RN10.7 | length 21.4
  Top Layer w0.35: R8.2 Q1.1 255.534,122.504 252.503,122.504 252.205,122.802 252.205,124.532 252.561,124.887 RN10.7 254.856,124.887 255.779,125.81 R9.1@262.622,125.81 ; R10.1 R9.1
SEY2: Q1.2 R8.1 U1.59 | length 36.2
  Top Layer w0.35: U1.59 v1@232.726,134.386 ; R8.1 Q1.2
  Bottom Layer w0.35: v1(232.726,134.386) 232.726,132.903 234.735,130.894 237.279,130.894 241.644,126.53 247.461,120.713 249.148,120.713 249.165,120.73 v1@257.996,120.73
  other v1: 258.174,120.705
SFY1: C21.1 RN10.2 RN11.7 U1.9 | length 28.9
  Top Layer w0.35: U1.9 236.216,126.334 236.921,125.629 241.269,125.629 242.435,126.795 243.637,126.795 244.125,127.283 v1(244.125,128.162) ; RN11.7 RN10.2
  Bottom Layer w0.35: v1(244.125,128.162) 244.125,125.957 245.227,124.855 v1(249.341,124.855) 249.973,124.855 250.52,124.308 v1(250.52,122.049)
SWCLK: SWD.3 U1.49 | length 20.5
  Top Layer w0.35: U1.49 231.755,139.386 232.327,138.814 v1(232.327,138.389)
  Bottom Layer w0.35: v1(232.327,138.389) 233.965,138.389 234.711,139.135 234.711,141.489 237.687,144.465 237.687,147.463 240.157,149.933 SWD.3
SWDIO: SWD.4 U1.46 | length 16.2
  Top Layer w0.35: U1.46 233.216,140.043 v1(233.801,139.459)
  Bottom Layer w0.35: v1(233.801,139.459) 233.801,141.476 237.087,144.762 237.087,147.899 237.617,148.429 SWD.4
TCK-Y: JTAG.9 RN1.5 RN3.5 RN3.6 RN3.7 RN8.4 | length 23
  Top Layer w0.35: RN3.5 RN3.6 RN3.7 279.977,134.285 279.717,134.545 279.717,142.261 280.262,142.806 RN1.5 RN8.4
  Bottom Layer w0.35: v1(281.774,142.794) 282.326,142.794 JTAG.9
TDI-Y: JTAG.5 RN1.7 RN2.7 RN8.2 UART.3 | length 51.9
  Top Layer w0.35: RN2.7 281.133,139.365 281.412,139.645 281.412,140.987 281.833,141.408 286.046,141.408 286.472,141.834 JTAG.5 ; RN1.7 RN8.2
  Bottom Layer w0.35: UART.3 273.304,124.522 277.127,128.345 277.127,131.554 283.941,138.368 283.941,139.618 283.393,140.165 281.803,140.165 281.155,140.813 281.155,141.425 281.085,141.494 281.085,144.174 281.377,144.466 v1(281.774,144.466) 283.39,144.466 286.022,141.834 JTAG.5
TDO-Y: JTAG.13 RN4.6 RN9.3 | length 10.3
  Top Layer w0.35: RN4.6 RN9.3 283.905,128.385 284.124,128.604 284.124,130.508 284.47,130.855 287.547,130.855 JTAG.13
TMS-Y: JTAG.7 RN1.6 RN2.6 RN8.3 | length 21.4
  Top Layer w0.35: RN2.6 281.257,138.545 281.862,139.151 281.862,140.656 282.138,140.932 286.728,140.932 JTAG.7 ; RN1.6 RN8.3
  Bottom Layer w0.35: v1(281.774,143.63) 282.61,143.63 286.946,139.294 JTAG.7
VEE: C5.2 C6.2 C7.2 R5.2 R6.2 R11.1 R14.1 RN13.8 T1.8 T2.8 T3.8 T4.8 T5.8 T6.8 T7.8 | length 65.1
  Top Layer w0.35: 273.259,137.478 273.259,134.112 273.259,130.556 ; T7.8 273.593,127.2 273.259,126.866 ; C7.2@275.76,124.767 273.949,124.767 273.259,125.457 273.259,126.866 ; R11.1 282.025,131.337 276.691,131.337 R14.1 274.672,130.998 T6.8 273.259,130.556 ; 273.259,126.866 273.259,130.556
  Top Layer w0.4: 273.256,141.473 273.256,147.617 273.721,148.082 T1.8 275.333,148.082 275.697,148.446 C6.2 ; 273.259,134.112 T5.8 ; 273.277,144.526 T2.8 ; T4.8 273.321,137.541 273.259,137.478 273.259,141.217 273.379,141.097 T3.8
  Top Layer w0.5: RN13.8@260.001,149.129 260.001,147.548 R5.2 264.48,147.505 C5.2 264.516,149.805 265.419,150.708 274.523,150.708 C6.2@275.357,149.874
VREF: JTAG.1 Pwer.1 Pwer.2 R15.2 | length 43
  Bottom Layer w0.5: v1(249.597,151.261) 251.152,152.816 270.272,152.816 270.739,153.283 273.183,153.283 Pwer.2 Pwer.1 278.469,152.146 280.688,149.928 280.688,148.668 282.442,146.914 JTAG.1
VREF1: R4.1 R15.1 U2.3 | length 5
  Top Layer w0.7: R15.1 R15.1@248.793,149.376 ; R4.1 R15.1@248.793,149.376 ; R15.1@248.793,149.409 R15.1@248.793,149.376 ; U2.3 248.817,149.352 R15.1@248.793,149.376
XTAL1: CY1.1 U1.5 Y1.2 | length 11.4
  Top Layer w0.35: CY1.1 232.105,120.152 232.105,123.571 232.105,126.05 234.216,128.161 U1.5
XTAL2: CY2.1 U1.6 Y1.1 | length 11.4
  Top Layer w0.35: U1.6 234.716,125.837 236.982,123.571 236.982,120.203 CY2.1
pads on no net: JTAG.2 RN3.1 RN3.8 RN9.4 T4.2 T4.7 T5.2 T5.7 U1.1 U1.2 U1.3 U1.4 U1.24 U1.26 U1.42 U1.50 U1.51 U1.52 U1.53 U1.54 U1.55 U1.56 U1.62 U5.3 U5.4

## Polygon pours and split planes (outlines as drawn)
GND on Top Layer "Top Layer-No Net" (solid, remove dead copper, pour order 4): 205.359,154.762 293.929,154.762 293.929,116.078 205.359,116.078
GND on Bottom Layer "Top Layer-No Net" (solid, remove dead copper, pour order 6): 205.359,154.762 293.929,154.762 293.929,116.078 205.359,116.078

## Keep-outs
Keep-Out Layer:
  the board outline again, w0.1

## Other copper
Top Layer:
  rectangle net NetC31_2: 209.095,127.738 211.524,142.982
  text "J-LINK  V9.5" at 220.922,151.884 h2

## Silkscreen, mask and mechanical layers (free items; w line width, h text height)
Top Overlay:
  rectangle: 273.412,149.59 273.75,150.837
  rectangle: 270.648,150.708 273.662,150.875
  rectangle: 270.427,149.425 273.748,149.72
  rectangle: 270.427,149.705 270.695,150.882
  rectangle: 283.276,123.703 285.541,124.02
  rectangle: 282.005,123.631 285.644,123.957
  rectangle: 280.806,123.703 281.958,123.861
  rectangle: 279.542,123.703 280.678,124.386
  rectangle: 279.598,125.959 280.655,126.793
  rectangle: 281.934,126.563 284.238,126.833
  rectangle: 279.63,126.706 285.58,126.904
  rectangle: 285.374,123.679 285.644,126.96
  rectangle: 284.222,123.679 284.405,126.88
  rectangle: 283.022,123.631 283.284,126.848
  rectangle: 281.822,123.591 282.061,126.88
  rectangle: 280.599,123.409 280.845,126.873
  rectangle: 279.309,123.528 279.646,126.971
  lines w0.254: 233.807,150.876 233.807,146.284 246.507,146.284 246.507,150.876 ; 236.253,146.318 236.253,150.833 ; 238.788,146.318 238.788,150.816 ; 241.406,146.251 241.406,150.799 ; 244.008,146.318 244.008,150.85 ; 279.198,126.952 279.198,123.716 279.272,123.641 285.707,123.641 285.726,123.66 285.726,126.952 285.744,126.971 279.309,126.971
  text "3.3V" at 270.69,149.731 h1.52
  text "~" at 274.012,149.699 h1.52
  text "VCC" at 287.434,147.938 h1.2
  text "3.3V" at 235.469,147.76 h1.52 r90
  text "SDIO" at 238.048,147.365 h1.52 r90
  text "GND" at 243.19,147.24 h1.52 r90
  text "SCLK" at 240.646,147.079 h1.52 r90
  text "NRST" at 245.77,146.577 h1.52 r90
  text "NTRST" at 287.311,145.195 h1.2
  text "TDI" at 287.294,142.701 h1.2
  text "TMS" at 287.283,140.143 h1.2
  text "TCK" at 287.294,137.604 h1.2
  text "RTCK" at 287.305,135.086 h1.2
  text "TDO" at 287.3,132.558 h1.2
  text "NSRST" at 287.322,129.995 h1.2
  text "RQ" at 287.317,127.472 h1.2
  text "ACK" at 287.328,124.927 h1.2
  text "5V" at 280.611,124.367 h1.52 r90
  text "3.3V" at 285.372,123.976 h1.52 r90
  text "TXD" at 283.029,123.939 h1.52 r90
  text "RXD" at 284.256,123.883 h1.52 r90
  text "GND" at 281.82,123.846 h1.52 r90
Top Solder:
  rectangle: 220.849,151.781 231.022,153.225
  lines w0.8: 206.121,153.949 293.091,153.949 293.123,153.917 293.123,116.898 292.927,116.701 206.295,116.701 206.215,116.782 206.215,153.856
Bottom Solder:
  lines w0.8: 206.105,116.887 206.287,116.704 292.93,116.704 293.114,116.889 293.114,153.918 292.969,154.063 206.105,154.063 206.105,116.887

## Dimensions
293.929,116.078 to 205.359,116.078 on Mechanical 1
205.359,154.762 to 205.359,116.078 on Mechanical 1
